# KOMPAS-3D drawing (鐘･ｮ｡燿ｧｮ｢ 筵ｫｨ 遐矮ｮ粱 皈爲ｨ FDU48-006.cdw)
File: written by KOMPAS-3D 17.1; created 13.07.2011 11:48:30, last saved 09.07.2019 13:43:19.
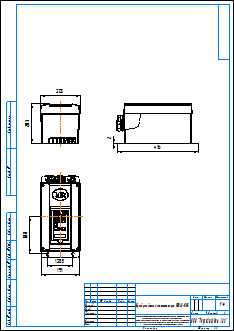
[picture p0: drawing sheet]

Title block, sheet 1: name: Преобразователи частоты серии FDU48-006; scale: 1:4; sheets: 1; sheet format: A3; stored path: \\adlc.lan\data\АДЛ_ПКД\3D-модели\Поставщики\Оборудование Emotron\Преобразователи частоты\Серия FDU 2.0\KOMPAS 2D\Преобразователи частоты серии FDU48-006.cdw

Views: Спереди 1
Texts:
  Рама для чертежей
  Лит-Масса-Масштаб
  Материал-Предприятие
  Масштаб
  Изм.
  Лист
  № докум.
  Подп.
  Дата
  Лит.
  Разраб.
  Пров.
  Т.контр.
  Листов
  Внимание! Данный продукт является объектом авторского права ООО «Торговый Дом АДЛ».
  Запрещается изменение, копирование, распространение
  (в том числе путем копирования на другие сайты и ресурсы в Интернете)
  или любое иное использование информации и объектов без предварительного
  согласия правообладателя (ООО «Торговый Дом АДЛ»).
  Н.контр.
  Утв.
  ООО "Торговый дом АДЛ"
  Изменение
  Номер документа
  Подпись
  Обозначение документа
  Наименование изделия
  Масса изделия по ГОСТ 2.109-73
  Порядковый номер листа
  Общее количество листов в документе
  Характер работы, выполненной лицом, подписавшим документ
  Наименование или индекс предприятия, выпускающего документ
  Инв. № подл.
  Подп. и дата
  Взам. инв. №
  Инв. № дубл.
  Инвентарный номер подлинника по ГОСТ 2.501-68
  Подпись принявшего подлинник в отдел технической документации
  Инвентарный номер подлинника, взамен которого выпущен данный подлинник
  Инвентарный номер дубликата по ГОСТ 2.502-68
  Подпись принявшего дубликат в отдел технической документации
  Справ. №
  Перв. примен.
  Обозначение документа, взамен или на основании которого выпущен данный документ
  Обозначение документа, в котором впервые записан данный документ
  Подпись лица, копировавшего чертеж
  Обозначение формата листа
  !Рама для чертежа
Dimensions and other numbers on the sheet: 203; 128,5; 191; 416; 2; 188; 1:4; 1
